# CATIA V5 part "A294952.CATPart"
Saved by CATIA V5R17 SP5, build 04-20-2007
Part number: 06F5001R2510N-158
Revision: B
Definition: A294952
Nomenclature: BACKSHELL, 90 DEG, SHRINK BOOT ACCOM, SELF-SEATING
Source: bought
Description: BACKSHELL, 90 DEG, SHRINK BOOT ACCOM, SELF-SEATING
Publications: "Logical Termination.1", "BCP", "BCP_generated(BCP)", "Face_generated(BCP)", "BaCP", "BaCP_generated(BaCP)", "Line.1_generated(BaCP)"
Material "Density=.2900": density 8027.17 kg/m3
Bounding box of the stored display mesh (mm): x -7.112 to 49.969, y -23.374 to 23.374, z -44.856 to 23.377
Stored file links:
  C:\Users\u305772\OneDrive - Gulfstream Aerospace\AD PAG\Harness\A294952.CATPart
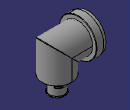
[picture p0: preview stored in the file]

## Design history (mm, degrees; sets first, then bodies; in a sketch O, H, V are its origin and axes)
Parameters
  PartNumber = "06F5001R2510N-158"
  OtherKeywords = "BACKSHELL, 90 DEG, SHRINK BOOT ACCOM, SELF-SEATING"
  Comments = "1.457 x .039 in THREAD, ELECTROLESS NICKEL."
  CAGECode = "07418"
  WeightComment = "SPEC"
  WeightSource = "SPEC"
  Volume = 1.91451e-05 (volume) {= smartVolume(Body1)}
  Density = 7916.45 (density)
  Weight = 0.334136 {= Volume *Density *2.20462262185}
  ExtraLength = 76.3524 mm {= E +F}
Set1
  Point1 "BCP": type Center, Curve edge [face of Shaft2 from Sketch7.L11 | face of Fillet1]
  Point2 "BaCP": type Center, Curve edge [face of Rib1 | face of Groove1 from Sketch4.L1]
  Point3: type Center, Curve edge [face of Groove1 from Sketch4.L2 | face of Slot1]
  Point4: (0, 0, 3.175), relative to Point2
  Line1: type PtPt, FirstPoint Point2, SecondPoint Point3
Body1 "PartBody" (main body)
  Sketch1 on zx-plane, origin (0, 0, 0), H (-1, 0, 0), V (0, 0, 1)
    point P1 (0, 0)
    line L1 (0, 0) -> (-31.496, 0)
    line L2 (-31.496, 0) -> (-31.496, -26.3144)
    point P2 (-31.496, -26.3144)
    point P4 (-31.496, -44.8564)
    length L1 = 31.496
    distance L1 P4 = 44.8564 {= F}
    distance P4 P2 = 18.542
    coincidence: P1 H, P1 V, P4 L2
    horizontal: L1 H
    perpendicularity: L1 L2
  Sketch2 on yz-plane, origin (0, 0, 0), H (0, 1, 0), V (0, 0, 1)
    circle A1 centre (0, 0) radius 18.5039
    construction line L1 (-18.5039, 0) -> (18.5039, 0)
    point P1 (-18.5039, 0)
    point P2 (18.5039, 0)
    length L1 = 37.0078
    coincidence: P1 A1, P1 H, A1 P2
    horizontal: L1 H
  Rib1: profile Sketch2, centre curve Sketch1
  Sketch3 on zx-plane, origin (0, 0, 0), H (-1, 0, 0), V (0, 0, 1)
    point P1 (-5.588, 18.5293)
    line L1 (-5.588, 18.5293) -> (-5.588, 23.3807)
    point P2 (-5.588, 23.3807)
    line L2 (-5.588, 23.3807) -> (3.4237, 23.3807)
    point P3 (3.4237, 23.3807)
    line L3 (3.4237, 23.3807) -> (3.937, 22.4917)
    point P4 (3.937, 22.4917)
    line L4 (3.937, 22.4917) -> (7.112, 22.4917)
    point P5 (7.112, 22.4917)
    line L5 (7.112, 22.4917) -> (7.112, 18.5293)
    point P6 (7.112, 18.5293)
    line L6 (7.112, 18.5293) -> (-5.588, 18.5293)
    axis line L7 (0, 0) -> (-5.588, 0)
    point P7 (-5.588, 0)
    point P8 (-5.588, -23.3807)
    point P9 (-5.588, -18.5293)
    construction line L8 (-5.588, -18.5293) -> (-5.588, -23.3807)
    point P10 (3.4237, -23.3807)
    construction line L9 (-5.588, -23.3807) -> (3.4237, -23.3807)
    point P11 (3.937, -22.4917)
    construction line L10 (3.4237, -23.3807) -> (3.937, -22.4917)
    point P12 (7.112, -22.4917)
    construction line L11 (3.937, -22.4917) -> (7.112, -22.4917)
    point P13 (7.112, -18.5293)
    construction line L12 (7.112, -22.4917) -> (7.112, -18.5293)
    construction line L13 (7.112, -18.5293) -> (-5.588, -18.5293)
    distance L5 L1 = 12.7
    length L4 = 3.175
    angle L4 L3 = 60
    distance L5 V = 7.112
    distance L6 L13 = 37.0586 {= `A THD` +.002 in}
    distance P5 P12 = 44.9834
    distance L4 L2 = 0.889
    vertical: L1 V, L5 V
    horizontal: L2 H, L4 H, L6 H, L7 H
    coincidence: P7 L1
    symmetry: P2 P8 L7, P1 P9 L7, L1 L8 L7, P3 P10 L7, L2 L9 L7, P4 P11 L7, L3 L10 L7, P5 P12 L7, L4 L11 L7, P6 P13 L7, L5 L12 L7, L6 L13 L7
  Shaft1: profile Sketch3, axis Sketch3.L7, angle 360
  Sketch4 on zx-plane, origin (0, 0, 0), H (-1, 0, 0), V (0, 0, 1)
    point P1 (0, 17.8689)
    line L1 (0, 17.8689) -> (-7.112, 17.8689)
    point P2 (-7.112, 17.8689)
    line L2 (-7.112, 17.8689) -> (-8.001, 16.9799)
    point P3 (-8.001, 16.9799)
    line L3 (-8.001, 16.9799) -> (-8.001, 0)
    point P4 (-8.001, 0)
    axis line L4 (-8.001, 0) -> (0, 0)
    line L5 (0, 0) -> (0, 17.8689)
    line L6 (0, 0) -> (-8.001, 0)
    point P5 (0, 0)
    point P6 (-8.001, 0)
    point P7 (-8.001, 0)
    point P8 (-8.001, -16.9799)
    construction line L7 (-8.001, -16.9799) -> (-8.001, 0)
    point P9 (-7.112, -17.8689)
    construction line L8 (-7.112, -17.8689) -> (-8.001, -16.9799)
    point P10 (0, -17.8689)
    construction line L9 (0, -17.8689) -> (-7.112, -17.8689)
    point P11 (0, 0)
    construction line L10 (0, 0) -> (0, -17.8689)
    construction line L11 (0, 0) -> (-8.001, 0)
    angle L1 L2 = 45
    length L1 = 7.112
    length L6 = 8.001
    distance L1 L9 = 35.7378 {= `A THD` -.05in}
    distance P8 P3 = 33.9598 (reference)
    coincidence: P1 V, P4 H, O L5, P4 L3, L6 L11
    horizontal: L1 H, L4 H, L6 H
    vertical: L3 V, L5 V
    symmetry: P6 P7 L4, P3 P8 L4, L3 L7 L4, P2 P9 L4, L2 L8 L4, P1 P10 L4, L1 L9 L4, P5 P11 L4, L5 L10 L4, L6 L11 L4
  Groove1: profile Sketch4, axis Sketch4.L4, angle 360
  Sketch5 on face of Groove1 from Sketch4.L3, origin (8.001, 0, 0), H (0, -1, 0), V (0, 0, 1)
    circle A1 centre (0, 0) radius 16.9799
    reference projected circle E1 centre (0, 0) radius 16.9799 from edge [face of Groove1 from Sketch4.L3 | face of Groove1 from Sketch4.L2]
    tangency: E1 A1
  Sketch6 on zx-plane, origin (0, 0, 0), H (-1, 0, 0), V (0, 0, 1)
    point P1 (-8.001, 0)
    line L1 (-8.001, 0) -> (-31.496, 0)
    line L2 (-31.496, 0) -> (-31.496, -26.3144)
    point P3 (-31.496, -26.3144)
    reference projected line E1 through (-31.496, 13.0492) direction (0, -1) from axis of face of Rib1
    reference projected line E2 (-24.7252, -26.3144) -> (-36.7241, -26.3144) from edge [face of Rib1 | face of Rib1]
    reference intersected line E3 (-8.001, -4.4755) -> (-8.001, 4.4755) from face of Groove1 from Sketch4.L3
    coincidence: P1 H, L2 E1, P3 E2, P1 E3
    horizontal: L1 H
  Slot1: profile Sketch5, centre curve Sketch6
  Sketch7 on zx-plane, origin (0, 0, 0), H (-1, 0, 0), V (0, 0, 1)
    axis line L1 (-31.496, 0) -> (-31.496, -44.8564)
    point P1 (-31.496, 0)
    point P2 (-31.496, -44.8564)
    point P3 (-23.5585, -44.8564)
    line L2 (-23.5585, -44.8564) -> (-23.5585, -25.0444)
    point P4 (-23.5585, -25.0444)
    line L3 (-23.5585, -25.0444) -> (-14.5161, -25.0444)
    line L4 (-21.3805, -26.3144) -> (-21.3805, -29.7434)
    line L5 (-21.3805, -29.7434) -> (-20.4216, -29.7434)
    point P5 (-20.4216, -29.7434)
    line L6 (-20.4216, -29.7434) -> (-20.4216, -31.0134)
    point P6 (-20.4216, -31.0134)
    line L7 (-20.4216, -31.0134) -> (-22.3393, -31.0134)
    point P7 (-22.3393, -31.0134)
    line L8 (-22.3393, -31.0134) -> (-22.3393, -43.5864)
    point P8 (-22.3393, -43.5864)
    line L9 (-22.3393, -43.5864) -> (-21.3805, -43.5864)
    point P9 (-21.3805, -43.5864)
    line L10 (-21.3805, -43.5864) -> (-21.3805, -44.8564)
    point P10 (-21.3805, -44.8564)
    line L11 (-21.3805, -44.8564) -> (-23.5585, -44.8564)
    point P11 (-39.4335, -25.0444)
    point P13 (-42.5704, -29.7434)
    point P14 (-42.5704, -31.0134)
    point P15 (-40.6527, -31.0134)
    construction line L12 (-39.4335, -25.0444) -> (-41.6116, -25.0444)
    construction line L13 (-41.6116, -25.0444) -> (-41.6116, -29.7434)
    construction line L14 (-41.6116, -29.7434) -> (-42.5704, -29.7434)
    construction line L15 (-42.5704, -29.7434) -> (-42.5704, -31.0134)
    construction line L16 (-42.5704, -31.0134) -> (-40.6527, -31.0134)
    point P16 (-39.4335, -44.8564)
    construction line L17 (-39.4335, -44.8564) -> (-39.4335, -25.0444)
    point P17 (-40.6527, -43.5864)
    construction line L18 (-40.6527, -31.0134) -> (-40.6527, -43.5864)
    point P18 (-41.6116, -43.5864)
    construction line L19 (-40.6527, -43.5864) -> (-41.6116, -43.5864)
    point P19 (-41.6116, -44.8564)
    construction line L20 (-41.6116, -43.5864) -> (-41.6116, -44.8564)
    construction line L21 (-41.6116, -44.8564) -> (-39.4335, -44.8564)
    reference projected line E1 through (-31.496, 13.0492) direction (0, -1) from axis of face of Rib1
    reference projected line E2 (-24.7252, -26.3144) -> (-36.7241, -26.3144) from edge [face of Rib1 | face of Rib1]
    reference projected line E3 (-24.7252, -26.3144) -> (-36.7241, -26.3144) from edge [face of Rib1 | face of Rib1]
    line L22 (-21.3805, -26.3144) -> (-14.5161, -26.3144)
    point P23 (-14.5161, -26.3144)
    line L23 (-14.5161, -26.3144) -> (-14.5161, -25.0444)
    point P24 (-14.5161, -25.0444)
    point P25 (-48.4759, -25.0444)
    point P26 (-48.4759, -26.3144)
    construction line L24 (-48.4759, -26.3144) -> (-48.4759, -25.0444)
    reference intersected line E4 (-24.7252, -26.3144) -> (-36.7241, -26.3144) from face of Rib1
    length L1 = 44.8564
    length L10 = 1.27
    length L6 = 1.27
    distance L2 L17 = 15.875
    distance L8 L18 = 18.3134
    distance L6 L15 = 22.1488
    distance E2 L5 = 3.429
    distance L3 E3 = 1.27
    distance L24 L23 = 33.9598 {= Sketch4.distance(P8 P3)}
    coincidence: H P1, L11 P2, E1 L1, L22 E4
    perpendicularity: L3 L2, L8 L7
    parallelism: L4 L2, L7 L5, L9 L7, L10 L6, L11 L7, L22 L12, L23 L6
    symmetry: P4 P11 L1, P5 P13 L1, P6 P14 L1, P7 P15 L1, L3 L12 L1, L4 L13 L1, L5 L14 L1, L6 L15 L1, L7 L16 L1, P3 P16 L1, L2 L17 L1, P8 P17 L1, L8 L18 L1, P9 P18 L1, L9 L19 L1, P10 P19 L1, L10 L20 L1, L11 L21 L1, L18 L15 L20, P24 P25 L1, P23 P26 L1, L23 L24 L1, L6 L8 L4
  Shaft2: profile Sketch7, axis Sketch7.L1, angle 360
  Sketch8 on zx-plane, origin (0, 0, 0), H (-1, 0, 0), V (0, 0, 1)
    arc A1 centre (-38.1635, -34.3154) radius 1.27 from (-38.1635, -33.0454) to (-38.1635, -35.5854) ccw
    arc A2 centre (-24.8285, -34.3154) radius 1.27 from (-24.8285, -35.5854) to (-24.8285, -33.0454) ccw
    construction line L1 (-24.8285, -34.3154) -> (-38.1635, -34.3154)
    reference projected line E1 (-29.7557, -31.0134) -> (-39.2045, -31.0134) from edge [face of Shaft2 from Sketch7.L6 | face of Shaft2 from Sketch7.L7]
    line L2 (-38.1635, -33.0454) -> (-24.8285, -33.0454)
    line L3 (-24.8285, -35.5854) -> (-38.1635, -35.5854)
    reference projected line E2 (-29.7557, -31.0134) -> (-39.2045, -31.0134) from edge [face of Shaft2 from Sketch7.L6 | face of Shaft2 from Sketch7.L7]
    construction line L4 (-31.496, -35.5854) -> (-31.496, -33.0454)
    point P7 (-31.496, -35.5854)
    point P8 (-31.496, -33.0454)
    reference projected line E3 through (-31.496, 13.0492) direction (0, -1) from axis of face of Shaft2 from Sketch7.L8
    distance L2 E2 = 2.032
    distance L2 L3 = 2.54
    distance A2 A1 = 15.875 {= `X DIA`}
    parallelism: E1 L1, L2 L1, L3 L1
    tangency: L2 A2, L2 A1, A1 L3, L3 A2
    midpoint: P7 L3, P8 L2
    perpendicularity: L4 L2
    coincidence: L4 E3
  Pocket1: profile Sketch8, direction (0, -1, 0), through (limit type 6), opposite side through (limit type 6)
  Fillet1: radius 0.508, on edge [face of Rib1 | face of Rib1]; edge [face of Shaft1 from Sketch3.L2 | face of Shaft1 from Sketch3.L1]; edge [face of Shaft2 from Sketch7.L5 | face of Shaft2 from Sketch7.L6]; edge [face of Shaft2 from Sketch7.L6 | face of Shaft2 from Sketch7.L7]; edge [face of Shaft2 from Sketch7.L9 | face of Shaft2 from Sketch7.L10]; edge [face of Shaft2 from Sketch7.L10 | face of Shaft2 from Sketch7.L11]; edge [face of Shaft2 from Sketch7.L11 | face of Shaft2 from Sketch7.L2]; edge [face of Rib1 | face of Shaft2]; edge [face of Shaft2 from Sketch7.L2 | face of Shaft2 from Sketch7.L3]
